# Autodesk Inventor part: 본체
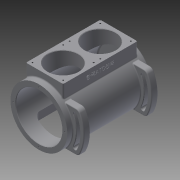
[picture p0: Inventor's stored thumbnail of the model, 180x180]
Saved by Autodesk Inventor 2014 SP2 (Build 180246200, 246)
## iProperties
Created: 2016-11
Part Number: 본체
Material: 알루미늄 6061
Document SubType Name: Modeling
Designer: mduedu
Density: 2.71 g/cm^3
Appearance: 기본값
Mass: 2488.99 g
Surface Area: 1764.74 cm^2
Volume: 918.447 cm^3
Author: mduedu
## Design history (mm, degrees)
sketch "스케치1"
  geometry: C1 r 65 at (0, 0); 1 further point
  constraints: 1 centre point, 1 coincident
  dimensions: "d119" = 130 diameter of C1
extrude "돌출1" new body sketch "스케치1" distance "d3" = 98; taper "d4" = 0 deg; dims "d132" = 97, "d133" = 0
feature "쉘1" dims "d120" = 12, "d134" = 8
node "작업 평면2"
sketch "스케치13"
  geometry: L1 (42.5, 85)-(-42.5, 85); L2 (-42.5, 85)-(-42.5, -85); L3 (-42.5, -85)-(42.5, -85); L4 (42.5, -85)-(42.5, 85); 2 further points
  constraints: 8 end point, 2 parallel, 1 horizontal, 1 midpoint, 1 perpendicular, 1 vertical alignment
  dimensions: "d122" = 170 distance of L1.end L2.end; "d124" = 85 distance of L2.end L3.end; "d125" = 85 distance from line of point (0, 0) L1 (= 0.5 x d122)
extrude "돌출11" join sketch "스케치13" stored distance "d126" = 10; taper "d127" = 0 deg
sketch "스케치14"
  geometry: L1 (65, 97)-(-65, 97) reference; C1 r 35 at (0, 42.5); 1 further point
  constraints: 1 centre point, 1 vertical alignment
  dimensions: "d128" = 70 diameter of C1; "d129" = 54.5 distance from line of C1.centre L1
extrude "돌출12" cut sketch "스케치14" stored distance "d130" = 10; taper "d131" = 0 deg
sketch "스케치15"
  geometry: C1 r 53 at (0, 0) reference; 1 further point
extrude "돌출13" cut sketch "스케치15" stored distance "d135" = 10; taper "d136" = 0 deg
chamfer "모따기1" distance "d54" = 1; stored, may be unused: second distance "d55" = 2, angle "d56" = 45 deg
sketch "스케치8"
  geometry: C1 r 23 at (0, 0); C2 r 65 at (0, 0) reference; 1 further point
  constraints: 1 centre point, 1 concentric
  dimensions: "d57" = 46 diameter of C1
extrude "돌출8" join sketch "스케치8" distance "d58" = 14; taper "d59" = 0 deg
hole "구멍3" diameter "d62" = 24; stored, may be unused: countersink angle "d66" = 90 deg, drill point angle "d68" = 0 deg; dims "d63" = 6, "d64" = 28, "d65" = 8, "d67" = 14, "d169" = 10, "d170" = 10
fillet "모깎기11" dims "d69" = 3
fillet "모깎기12" dims "d70" = 3
fillet "모깎기13" dims "d71" = 0.3
chamfer "모따기2" distance "d72" = 1; stored, may be unused: second distance "d73" = 2, angle "d74" = 45 deg
node "작업 평면3"
sketch "스케치16"
  geometry: L1 (-42.5, -80)-(47.5, -80); L2 (-42.5, -80)-(21.14, -16.36); L3 (-42.5, -80)-(21.14, -143.64); L4 (3.462, -34.038)-(34.879, -34.038); L5 (3.462, -125.962)-(34.879, -125.962); A1 r 65 centre (-42.5, -80) between (3.462, -34.038) and (3.462, -125.962) reference; A2 r 90 centre (-42.5, -80) between (34.879, -125.962) and (34.879, -34.038); A3 r 90 centre (-42.5, -80) between (34.879, -34.038) and (34.879, -125.962); A4 r 65 centre (-42.5, -80) between (3.462, -125.962) and (3.462, -34.038); 1 further point
  constraints: 11 point on circle, 10 end point, 3 centre point, 2 parallel, 2 point on line, 1 coincident, 1 horizontal
  dimensions: "d140" = 45 deg angle of L3 L1; "d141" = 45 deg angle of L2 L1; "d142" = 25 radial gap between concentric circles of A1 A2
extrude "돌출14" join sketch "스케치16" distance "d143" = 15; taper "d144" = 0 deg
sketch "스케치17"
  geometry: L1 (-42.5, -80)-(34.414, -80); L2 (-42.5, -80)-(27.208, -47.495); L3 (-42.5, -80)-(27.208, -112.505); L4 (34.879, -34.038)-(3.462, -34.038) reference; L5 (3.462, -125.962)-(34.879, -125.962) reference; A1 r 65 centre (-42.5, -80) between (3.462, -34.038) and (3.462, -125.962) reference; A2 r 76.914 centre (-42.5, -80) between (19.17, -125.962) and (19.17, -34.038); A3 r 4 centre (27.208, -47.495) between (23.582, -49.185) and (30.833, -45.804); A4 r 4 centre (27.208, -112.505) between (30.833, -114.196) and (23.582, -110.815); A5 r 80.914 centre (-42.5, -80) between (30.833, -114.196) and (30.833, -45.804); A6 r 72.914 centre (-42.5, -80) between (23.582, -110.815) and (23.582, -49.185); 1 further point
  constraints: 13 point on circle, 6 end point, 5 centre point, 5 coincident, 3 midpoint, 2 point on line, 1 equal radius, 1 horizontal
  dimensions: "d145" = 25 deg angle of L1 L3; "d146" = 25 deg angle of L2 L1; "d147" = 8 diameter of A3
extrude "돌출15" cut sketch "스케치17" stored distance "d150" = 15; taper "d151" = 0 deg
fillet "모깎기17" dims "d152" = 10
fillet "모깎기18" dims "d153" = 2
fillet "모깎기19" dims "d154" = 2
chamfer "모따기4" distance "d155" = 1; stored, may be unused: second distance "d156" = 2, angle "d157" = 45 deg
fillet "모깎기20" dims "d159" = 3
fillet "모깎기21" dims "d160" = 3
fillet "모깎기22" dims "d161" = 3
node "작업 평면4"
sketch "스케치18"
  geometry: L1 (-42.5, 65)-(42.5, 65); L2 (42.5, 65)-(42.5, -65); L3 (42.5, -65)-(-42.5, -65); L4 (-42.5, -65)-(-42.5, 65); 2 further points
  constraints: 8 end point, 2 parallel, 1 horizontal, 1 midpoint, 1 perpendicular, 1 vertical alignment
  dimensions: "d162" = 130 distance of L1.end L2.end; "d164" = 85 distance of L2.end L3.end; "d165" = 65 distance from line of point (0, 0) L1 (= 0.5 x d162)
extrude "돌출16" cut sketch "스케치18" stored distance "d166" = 15; taper "d167" = 0 deg
fillet "모깎기23" dims "d168" = 10
fillet "모깎기24" dims "d173" = 3
sketch "스케치19"
  geometry: 4 further points
  constraints: 4 other
hole "구멍6" sketch "스케치19" at (0, -59), (59, 0), (-59, 0), (0, 59) diameter "d174" = 3.242; stored, may be unused: countersink angle "d178" = 90 deg, drill point angle "d180" = 120 deg; dims "d175" = 7, "d176" = 4, "d177" = 2, "d179" = 9
sketch "스케치20"
  geometry: L1 (35, -77.5)-(-35, -77.5); L2 (-35, -77.5)-(-35, -7.5); L3 (-35, -7.5)-(35, -7.5); L4 (35, -7.5)-(35, -77.5); L5 (35, -77.5)-(-35, -7.5); L6 (-35, -77.5)-(35, -7.5); C1 r 36 at (0, -42.5) reference; 5 further points
  constraints: 12 end point, 4 coincident, 2 midpoint, 2 parallel, 1 horizontal, 1 perpendicular
  dimensions: "d181" = 70 distance of L2.end L3.end; "d182" = 70 distance of L1.end L2.end
hole "구멍7" sketch "스케치20" at (-35, -77.5), (-35, -7.5), (35, -7.5), (35, -77.5) diameter "d183" = 3.242; stored, may be unused: countersink angle "d187" = 90 deg, drill point angle "d189" = 118 deg; dims "d184" = 7, "d185" = 4, "d186" = 2, "d188" = 9
sketch "스케치21"
  geometry: L1 (164, 0)-(0, 0) reference; L2 (-3, 0)-(-3, -24.649) reference; 3 further points
  constraints: 1 midpoint, 1 vertical alignment, 1 other
  dimensions: "d190" = 15 distance from line of point (82, -15) L1; "d191" = 85 distance from line of point (82, 0) L2 (derived)
feature "엠보싱2" sketch "스케치21" dims "d3" = 98, "d4" = 0, "d119" = 130, "d132" = 97, "d133" = 0, "d192" = 0.5, "d193" = 0
node "솔리드1"
mirror "대칭5"
mirror "대칭6"
mirror "대칭7"
